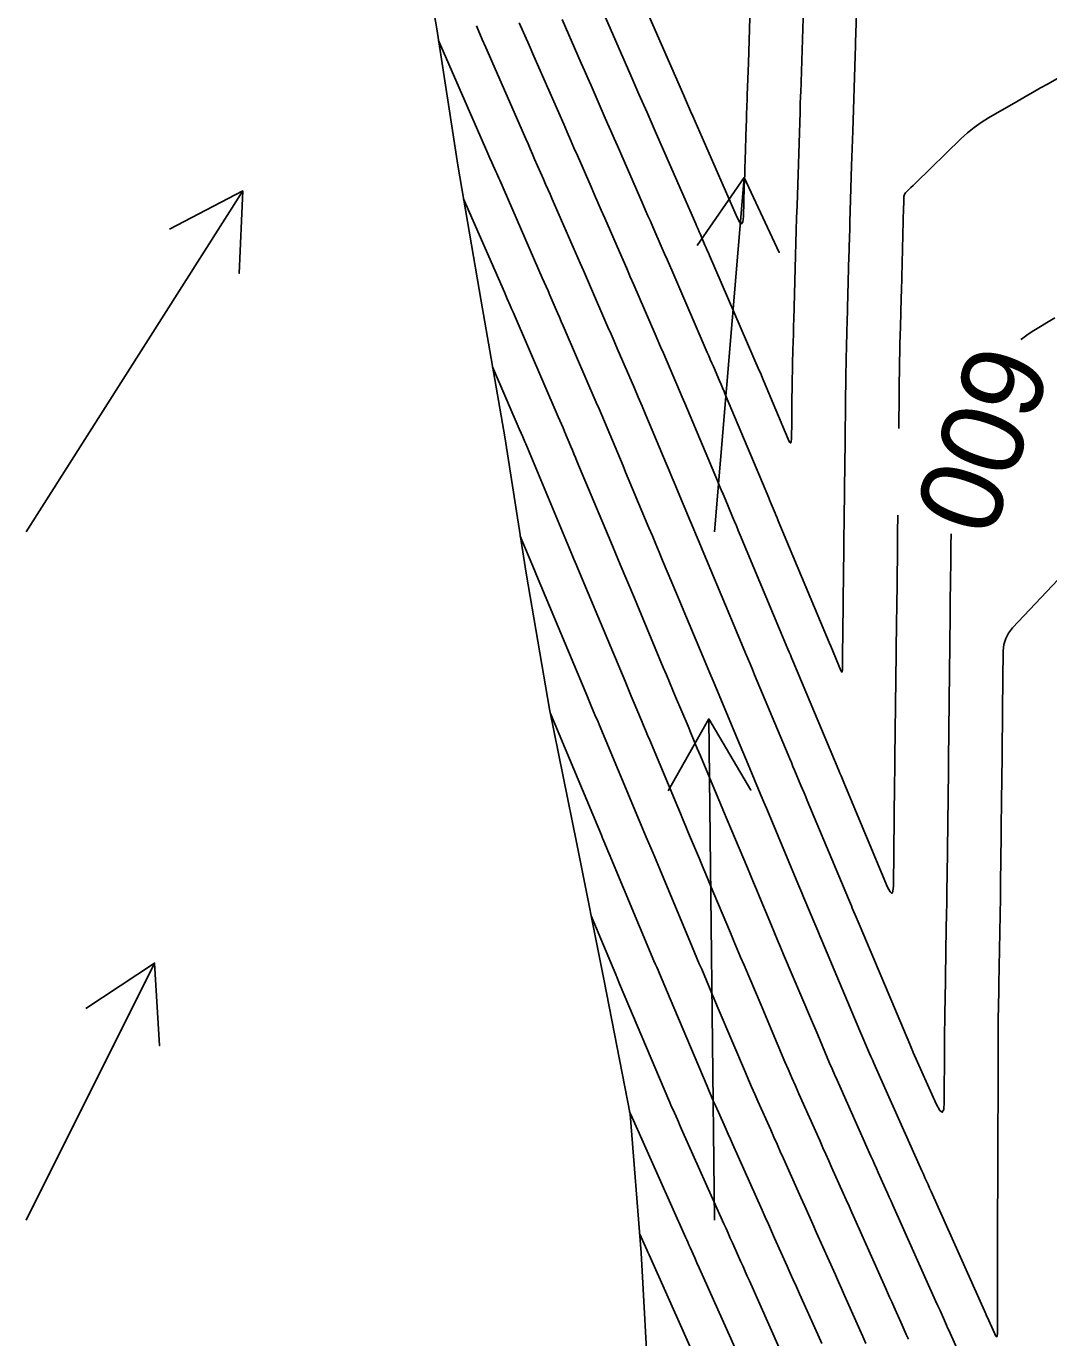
# Model space of a CAD drawing. Extents: x 954385 to 988206, y 1868364 to 1924553.
# Drawn here: x 957957.1 to 958031.4, y 1918710.4 to 1918805.7 of the extents above; entities that cross this region are included whole.
import ezdxf

# ---------------------------------------------------------------- set-up
doc = ezdxf.new("R2010")
doc.units = 0
for name, color, linetype in [('Ex_Contour Labels', 7, 'Continuous'), ('Ex_Major Contours', 7, 'Continuous'), ('Ex_Minor Contours', 7, 'Continuous'), ('Perimeter', 7, 'Continuous'), ('Slopes', 7, 'Continuous')]:
    doc.layers.add(name, color=color, linetype=linetype)

msp = doc.modelspace()

# ---------------------------------------------------------------- linework, layer by layer
at = {"layer": 'Ex_Major Contours'}
for points in [[(957989.838, 1918805.686), (957990.266, 1918804.707), (957990.523, 1918804.12), (957993.431, 1918797.475), (957993.591, 1918797.11), (957993.75, 1918796.745), (957993.91, 1918796.38), (957994.07, 1918796.015), (957994.708, 1918794.555), (957994.868, 1918794.19), (957995.028, 1918793.825), (957995.188, 1918793.46), (957995.347, 1918793.095), (957997.384, 1918788.442), (957997.609, 1918787.927), (957997.834, 1918787.413), (957998.057, 1918786.898), (957998.281, 1918786.382), (957999.173, 1918784.321), (957999.396, 1918783.806), (957999.619, 1918783.291), (957999.842, 1918782.775), (958000.064, 1918782.26), (958001.316, 1918779.367), (958001.595, 1918778.719), (958001.872, 1918778.07), (958002.148, 1918777.42), (958002.422, 1918776.769), (958003.623, 1918773.902), (958003.841, 1918773.382), (958004.059, 1918772.862), (958004.277, 1918772.342), (958004.495, 1918771.822), (958005.366, 1918769.743), (958005.584, 1918769.223), (958005.801, 1918768.703), (958006.019, 1918768.183), (958006.237, 1918767.663), (958008.244, 1918762.868), (958008.737, 1918761.69), (958009.395, 1918760.12), (958009.559, 1918759.728), (958009.724, 1918759.335), (958009.888, 1918758.943), (958010.052, 1918758.55), (958012.49, 1918752.728), (958012.606, 1918752.452), (958012.722, 1918752.176), (958012.837, 1918751.9), (958012.953, 1918751.624), (958013.416, 1918750.519), (958013.532, 1918750.243), (958013.647, 1918749.967), (958013.763, 1918749.691), (958013.879, 1918749.415), (958016.87, 1918742.276), (958016.94, 1918742.108), (958017.011, 1918741.94), (958017.081, 1918741.773), (958017.151, 1918741.605), (958017.432, 1918740.934), (958017.503, 1918740.766), (958017.573, 1918740.599), (958017.644, 1918740.431), (958017.714, 1918740.264), (958021.331, 1918731.715), (958021.482, 1918731.358), (958021.508, 1918731.298), (958021.533, 1918731.239), (958021.559, 1918731.18), (958021.585, 1918731.121), (958023.254, 1918727.387), (958023.505, 1918726.913), (958023.685, 1918726.775), (958023.793, 1918726.974), (958023.831, 1918727.509), (958023.841, 1918731.38), (958023.841, 1918731.569), (958023.843, 1918731.757), (958023.845, 1918731.946), (958023.848, 1918732.134), (958023.862, 1918732.954), (958023.864, 1918733.109), (958023.867, 1918733.265), (958023.869, 1918733.421), (958023.872, 1918733.577), (958023.885, 1918734.356), (958023.89, 1918734.667), (958023.893, 1918734.823), (958023.982, 1918740.161), (958023.997, 1918741.103), (958024.011, 1918742.044), (958024.024, 1918742.986), (958024.036, 1918743.927), (958024.129, 1918751.585), (958024.136, 1918752.166), (958024.138, 1918752.343), (958024.138, 1918752.365), (958024.214, 1918758.741), (958024.218, 1918759.127), (958024.223, 1918759.512), (958024.227, 1918759.898), (958024.232, 1918760.283), (958024.268, 1918763.368), (958024.297, 1918765.809), (958024.303, 1918766.345), (958024.309, 1918766.88), (958024.315, 1918767.416), (958024.322, 1918767.951), (958024.332, 1918768.784)], [(958029.404, 1918782.901), (958029.447, 1918782.938), (958029.828, 1918783.225), (958030.23, 1918783.488), (958031.876, 1918784.488)], [(957995.217, 1918755.74), (957998.918, 1918746.911), (957999.013, 1918746.683), (957999.109, 1918746.455), (957999.3, 1918745.999), (957999.395, 1918745.771), (957999.491, 1918745.543), (958002.743, 1918737.778), (958002.84, 1918737.546), (958002.938, 1918737.315), (958003.035, 1918737.083), (958003.133, 1918736.852), (958003.916, 1918735.002), (958006.6, 1918728.657), (958006.75, 1918728.306), (958006.901, 1918727.956), (958007.053, 1918727.607), (958007.208, 1918727.259), (958007.83, 1918725.867), (958007.985, 1918725.519), (958008.141, 1918725.171), (958008.296, 1918724.823), (958008.452, 1918724.475), (958010.605, 1918719.651), (958010.831, 1918719.145), (958011.057, 1918718.639), (958011.283, 1918718.133), (958011.509, 1918717.627), (958012.414, 1918715.603), (958012.64, 1918715.097), (958012.866, 1918714.591), (958013.092, 1918714.085), (958013.318, 1918713.579), (958014.64, 1918710.621), (958014.93, 1918709.973)]]:
    msp.add_lwpolyline(points, dxfattribs=at)
at = {"layer": 'Ex_Minor Contours'}
for points in [[(958009.811, 1918809.565), (958009.598, 1918803.001), (958009.521, 1918800.652), (958009.509, 1918800.281), (958009.497, 1918799.91), (958009.473, 1918799.169), (958009.461, 1918798.798), (958009.449, 1918798.427), (958009.367, 1918795.907), (958009.351, 1918795.426), (958009.336, 1918794.944), (958009.32, 1918794.462), (958009.304, 1918793.981), (958009.235, 1918791.851), (958009.194, 1918791.458), (958009.106, 1918791.313), (958008.971, 1918791.415), (958008.788, 1918791.765), (958005.569, 1918799.122), (958005.404, 1918799.498), (958004.966, 1918800.501), (958004.911, 1918800.626), (958001.612, 1918808.165)], [(958017.511, 1918808.051), (958017.395, 1918804.48), (958017.387, 1918804.235), (958017.379, 1918803.991), (958017.371, 1918803.746), (958017.363, 1918803.501), (958017.185, 1918798.045), (958017.165, 1918797.411), (958017.144, 1918796.778), (958017.124, 1918796.144), (958017.103, 1918795.511), (958016.997, 1918792.249), (958016.989, 1918791.979), (958016.98, 1918791.71), (958016.972, 1918791.44), (958016.965, 1918791.171), (958016.936, 1918790.092), (958016.928, 1918789.823), (958016.921, 1918789.553), (958016.914, 1918789.284), (958016.906, 1918789.014), (958016.802, 1918785.205), (958016.792, 1918784.824), (958016.781, 1918784.444), (958016.771, 1918784.063), (958016.761, 1918783.682), (958016.719, 1918782.159), (958016.709, 1918781.778), (958016.701, 1918781.397), (958016.694, 1918781.016), (958016.689, 1918780.636), (958016.655, 1918777.856), (958016.648, 1918777.266), (958016.641, 1918776.676), (958016.634, 1918776.085), (958016.627, 1918775.495), (958016.585, 1918772.075), (958016.579, 1918771.598), (958016.574, 1918771.121), (958016.568, 1918770.643), (958016.562, 1918770.166), (958016.538, 1918768.041), (958016.533, 1918767.672), (958016.529, 1918767.302), (958016.525, 1918766.933), (958016.52, 1918766.563), (958016.503, 1918765.085), (958016.499, 1918764.715), (958016.494, 1918764.346), (958016.49, 1918763.976), (958016.486, 1918763.606), (958016.441, 1918759.895), (958016.438, 1918759.641), (958016.435, 1918759.386), (958016.429, 1918758.878), (958016.422, 1918758.781), (958016.403, 1918758.746), (958016.371, 1918758.771), (958016.328, 1918758.858), (958015.588, 1918760.625), (958015.479, 1918760.885), (958011.772, 1918769.742), (958011.714, 1918769.879), (958011.656, 1918770.017), (958011.599, 1918770.155), (958011.541, 1918770.292), (958011.253, 1918770.98), (958011.137, 1918771.255), (958011.08, 1918771.393), (958007.948, 1918778.866), (958007.839, 1918779.125), (958007.729, 1918779.385), (958007.618, 1918779.644), (958007.507, 1918779.902), (958007.06, 1918780.937), (958006.948, 1918781.195), (958006.836, 1918781.454), (958006.724, 1918781.712), (958006.612, 1918781.971), (958004.031, 1918787.935), (958003.859, 1918788.331), (958003.688, 1918788.726), (958003.515, 1918789.122), (958003.342, 1918789.517), (958002.65, 1918791.098), (958002.477, 1918791.494), (958002.304, 1918791.889), (958002.131, 1918792.284), (958001.958, 1918792.68), (958000.084, 1918796.963), (957999.844, 1918797.511), (957999.605, 1918798.059), (957999.365, 1918798.607), (957999.125, 1918799.155), (957998.166, 1918801.347), (957997.926, 1918801.895), (957997.686, 1918802.443), (957997.446, 1918802.991), (957997.206, 1918803.539), (957996.062, 1918806.154)], [(957998.875, 1918807.072), (958001.059, 1918802.083), (958001.353, 1918801.409), (958001.648, 1918800.736), (958002.237, 1918799.389), (958002.385, 1918799.052), (958002.532, 1918798.716), (958002.679, 1918798.379), (958002.827, 1918798.042), (958005.774, 1918791.305), (958005.858, 1918791.113), (958005.942, 1918790.921), (958006.026, 1918790.729), (958006.111, 1918790.537), (958006.447, 1918789.768), (958006.531, 1918789.576), (958006.615, 1918789.383), (958006.698, 1918789.191), (958006.782, 1918788.999), (958010.391, 1918780.659), (958010.471, 1918780.474), (958010.604, 1918780.166), (958010.631, 1918780.104), (958010.657, 1918780.042), (958010.684, 1918779.98), (958010.71, 1918779.918), (958012.49, 1918775.67), (958012.596, 1918775.458), (958012.672, 1918775.396), (958012.719, 1918775.482), (958012.737, 1918775.718), (958012.752, 1918776.959), (958012.756, 1918777.269), (958012.76, 1918777.579), (958012.764, 1918777.889), (958012.767, 1918778.199), (958012.787, 1918779.786), (958012.792, 1918780.154), (958012.799, 1918780.522), (958012.807, 1918780.89), (958012.816, 1918781.258), (958012.858, 1918782.807), (958012.869, 1918783.188), (958012.879, 1918783.568), (958012.889, 1918783.949), (958012.9, 1918784.33), (958013.027, 1918789.017), (958013.053, 1918789.926), (958013.079, 1918790.834), (958013.107, 1918791.742), (958013.136, 1918792.65), (958013.355, 1918799.414), (958013.372, 1918799.933), (958013.396, 1918800.654), (958013.401, 1918800.822), (958013.604, 1918807.033)], [(957992.95, 1918805.92), (957993.663, 1918804.292), (957994.019, 1918803.477), (957994.375, 1918802.663), (957996.18, 1918798.538), (957996.429, 1918797.97), (957996.677, 1918797.402), (957996.926, 1918796.834), (957997.175, 1918796.266), (957998.169, 1918793.993), (957998.417, 1918793.425), (957998.666, 1918792.857), (957998.915, 1918792.289), (957999.163, 1918791.721), (958000.238, 1918789.267), (958000.499, 1918788.668), (958000.76, 1918788.069), (958001.021, 1918787.47), (958001.28, 1918786.871), (958002.833, 1918783.283), (958003.03, 1918782.828), (958003.227, 1918782.372), (958003.424, 1918781.917), (958003.621, 1918781.461), (958004.409, 1918779.639), (958004.606, 1918779.184), (958004.801, 1918778.727), (958004.994, 1918778.27), (958005.187, 1918777.813), (958007.352, 1918772.647), (958007.489, 1918772.319), (958007.627, 1918771.99), (958007.765, 1918771.661), (958007.903, 1918771.332), (958008.453, 1918770.018), (958008.591, 1918769.689), (958008.729, 1918769.36), (958008.867, 1918769.031), (958009.004, 1918768.703), (958011.867, 1918761.865), (958012.477, 1918760.408), (958012.564, 1918760.2), (958012.651, 1918759.992), (958012.738, 1918759.784), (958012.825, 1918759.576), (958016.17, 1918751.587), (958016.251, 1918751.395), (958016.332, 1918751.202), (958016.534, 1918750.72), (958016.655, 1918750.431), (958019.712, 1918743.136), (958019.892, 1918742.774), (958020.023, 1918742.667), (958020.104, 1918742.815), (958020.135, 1918743.218), (958020.225, 1918750.666), (958020.229, 1918750.978), (958020.234, 1918751.368), (958020.235, 1918751.523), (958020.236, 1918751.601), (958020.248, 1918752.579), (958020.337, 1918760.107), (958020.347, 1918760.914), (958020.356, 1918761.721), (958020.366, 1918762.528), (958020.375, 1918763.335), (958020.424, 1918767.494), (958020.432, 1918768.178), (958020.44, 1918768.863), (958020.455, 1918770.152)], [(958020.531, 1918776.453), (958020.591, 1918781.443), (958020.597, 1918781.858), (958020.605, 1918782.273), (958020.614, 1918782.688), (958020.624, 1918783.104), (958020.669, 1918784.764), (958020.681, 1918785.179), (958020.692, 1918785.595), (958020.703, 1918786.01), (958020.715, 1918786.425), (958020.88, 1918792.521), (958020.881, 1918792.553), (958020.882, 1918792.586), (958020.883, 1918792.618), (958020.884, 1918792.651), (958020.893, 1918792.91), (958020.905, 1918793.297), (958020.914, 1918793.369), (958020.936, 1918793.436), (958020.971, 1918793.497), (958021.018, 1918793.553), (958021.412, 1918793.938), (958021.579, 1918794.102), (958021.747, 1918794.265), (958025.06, 1918797.506), (958025.518, 1918797.927), (958026.001, 1918798.317), (958026.507, 1918798.675), (958027.037, 1918799.002), (958029.205, 1918800.245), (958029.747, 1918800.556), (958030.289, 1918800.866), (958030.831, 1918801.177), (958031.373, 1918801.488), (958037.89, 1918805.224)], [(958032.523, 1918765.905), (958028.798, 1918761.954), (958028.507, 1918761.586), (958028.298, 1918761.185), (958028.171, 1918760.752), (958028.124, 1918760.286), (958028.075, 1918756.046), (958028.071, 1918755.761), (958028.068, 1918755.476), (958028.064, 1918755.191), (958028.061, 1918754.906), (958028.048, 1918753.766), (958028.044, 1918753.481), (958028.041, 1918753.197), (958028.037, 1918752.912), (958028.034, 1918752.627), (958027.994, 1918749.382), (958027.986, 1918748.746), (958027.979, 1918748.11), (958027.971, 1918747.474), (958027.963, 1918746.838), (958027.922, 1918743.461), (958027.919, 1918743.191), (958027.915, 1918742.92), (958027.911, 1918742.649), (958027.907, 1918742.379), (958027.802, 1918736.076), (958027.791, 1918735.388), (958027.779, 1918734.699), (958027.756, 1918733.322), (958027.751, 1918732.977), (958027.747, 1918732.633), (958027.744, 1918732.289), (958027.743, 1918731.944), (958027.717, 1918721.437), (958027.712, 1918719.555), (958027.711, 1918719.085), (958027.71, 1918718.614), (958027.709, 1918718.144), (958027.707, 1918717.673), (958027.694, 1918712.593), (958027.694, 1918712.359), (958027.693, 1918712.124), (958027.693, 1918711.89), (958027.692, 1918711.655), (958027.69, 1918710.714), (958027.678, 1918710.537), (958027.642, 1918710.471), (958027.582, 1918710.516), (958027.499, 1918710.674), (958026.944, 1918711.917), (958026.912, 1918711.988), (958026.848, 1918712.132), (958022.879, 1918721.016), (958022.767, 1918721.267), (958022.655, 1918721.517), (958022.431, 1918722.018), (958022.319, 1918722.269), (958022.207, 1918722.52), (958018.814, 1918730.116), (958018.71, 1918730.349), (958018.608, 1918730.583), (958018.507, 1918730.818), (958018.406, 1918731.053), (958017.71, 1918732.7), (958014.938, 1918739.252), (958014.792, 1918739.597), (958014.646, 1918739.942), (958014.501, 1918740.288), (958014.356, 1918740.633), (958013.777, 1918742.015), (958013.632, 1918742.361), (958013.488, 1918742.707), (958013.343, 1918743.052), (958013.198, 1918743.398), (958011.103, 1918748.399), (958010.912, 1918748.854), (958010.72, 1918749.31), (958010.529, 1918749.766), (958010.338, 1918750.222), (958009.574, 1918752.045), (958009.383, 1918752.501), (958009.192, 1918752.957), (958009.001, 1918753.413), (958008.81, 1918753.869), (958007.279, 1918757.524), (958007.038, 1918758.101), (958006.796, 1918758.678), (958006.555, 1918759.255), (958006.313, 1918759.832), (958005.105, 1918762.717), (958004.38, 1918764.448), (958003.372, 1918766.858), (958003.123, 1918767.452), (958002.874, 1918768.046), (958002.625, 1918768.64), (958002.376, 1918769.234), (958000.877, 1918772.814), (958000.684, 1918773.274), (958000.491, 1918773.734), (958000.298, 1918774.194), (958000.106, 1918774.654), (957999.334, 1918776.494), (957999.141, 1918776.954), (957998.946, 1918777.413), (957998.75, 1918777.872), (957998.553, 1918778.33), (957996.286, 1918783.572), (957996.148, 1918783.891), (957996.01, 1918784.209), (957995.872, 1918784.527), (957995.735, 1918784.846), (957995.183, 1918786.119), (957995.045, 1918786.438), (957994.907, 1918786.756), (957994.768, 1918787.074), (957994.629, 1918787.392), (957991.531, 1918794.47), (957991.46, 1918794.632), (957991.39, 1918794.793), (957991.319, 1918794.955), (957991.248, 1918795.117), (957990.965, 1918795.765), (957990.823, 1918796.088), (957990.681, 1918796.412), (957987.086, 1918804.628)], [(957988.907, 1918793.121), (957991.875, 1918786.342), (957991.928, 1918786.221), (957991.981, 1918786.099), (957992.033, 1918785.978), (957992.086, 1918785.856), (957992.296, 1918785.37), (957992.401, 1918785.127), (957992.507, 1918784.884), (957995.79, 1918777.293), (957995.905, 1918777.025), (957996.02, 1918776.757), (957996.134, 1918776.488), (957996.247, 1918776.22), (957996.698, 1918775.144), (957996.81, 1918774.875), (957996.923, 1918774.606), (957997.036, 1918774.337), (957997.148, 1918774.068), (957999.604, 1918768.208), (957999.775, 1918767.799), (957999.947, 1918767.389), (958000.118, 1918766.98), (958000.29, 1918766.57), (958001.318, 1918764.113), (958001.661, 1918763.294), (958003.42, 1918759.092), (958003.645, 1918758.557), (958003.869, 1918758.021), (958004.093, 1918757.486), (958004.317, 1918756.951), (958005.214, 1918754.809), (958005.438, 1918754.274), (958005.662, 1918753.739), (958005.887, 1918753.203), (958006.111, 1918752.668), (958007.261, 1918749.925), (958007.527, 1918749.289), (958007.794, 1918748.653), (958008.06, 1918748.018), (958008.326, 1918747.382), (958009.526, 1918744.519), (958009.745, 1918743.996), (958009.965, 1918743.473), (958010.184, 1918742.949), (958010.403, 1918742.426), (958011.28, 1918740.332), (958011.499, 1918739.809), (958011.719, 1918739.285), (958011.94, 1918738.763), (958012.161, 1918738.24), (958014.113, 1918733.626), (958014.635, 1918732.392), (958015.331, 1918730.748), (958015.506, 1918730.337), (958015.683, 1918729.927), (958015.862, 1918729.518), (958016.043, 1918729.11), (958018.508, 1918723.591), (958018.641, 1918723.292), (958018.775, 1918722.994), (958018.908, 1918722.696), (958019.041, 1918722.398), (958019.573, 1918721.206), (958019.706, 1918720.908), (958019.839, 1918720.61), (958019.973, 1918720.312), (958020.106, 1918720.014), (958023.205, 1918713.076), (958023.365, 1918712.72), (958023.524, 1918712.364), (958023.842, 1918711.652), (958023.921, 1918711.474), (958024.001, 1918711.296), (958024.08, 1918711.117), (958024.16, 1918710.939), (958027.83, 1918702.717)], [(957991.013, 1918780.913), (957993.027, 1918776.255), (957993.061, 1918776.178), (957993.094, 1918776.1), (957993.127, 1918776.023), (957993.16, 1918775.945), (957993.355, 1918775.478), (957993.42, 1918775.322), (957996.831, 1918767.182), (957996.925, 1918766.957), (957997.019, 1918766.732), (957997.114, 1918766.507), (957997.208, 1918766.282), (957997.962, 1918764.482), (958000.644, 1918758.076), (958000.793, 1918757.72), (958000.941, 1918757.364), (958001.09, 1918757.009), (958001.239, 1918756.653), (958001.835, 1918755.231), (958001.984, 1918754.875), (958002.133, 1918754.52), (958002.282, 1918754.164), (958002.431, 1918753.809), (958004.473, 1918748.936), (958004.67, 1918748.466), (958004.867, 1918747.997), (958005.064, 1918747.527), (958005.26, 1918747.057), (958006.048, 1918745.178), (958006.245, 1918744.708), (958006.441, 1918744.239), (958006.638, 1918743.769), (958006.835, 1918743.299), (958008.302, 1918739.796), (958008.547, 1918739.212), (958008.792, 1918738.629), (958009.038, 1918738.045), (958009.285, 1918737.462), (958010.518, 1918734.548), (958011.258, 1918732.799), (958012.255, 1918730.443), (958012.504, 1918729.856), (958012.757, 1918729.271), (958013.013, 1918728.687), (958013.271, 1918728.105), (958014.809, 1918724.662), (958015.02, 1918724.191), (958015.23, 1918723.72), (958015.44, 1918723.249), (958015.65, 1918722.778), (958016.491, 1918720.895), (958016.702, 1918720.424), (958016.912, 1918719.953), (958017.122, 1918719.482), (958017.333, 1918719.011), (958019.563, 1918714.02), (958019.714, 1918713.682), (958019.865, 1918713.344), (958020.016, 1918713.005), (958020.167, 1918712.667), (958020.772, 1918711.315), (958020.923, 1918710.977), (958021.074, 1918710.639), (958021.225, 1918710.3)], [(958018.146, 1918709.982), (958017.924, 1918710.48), (958017.701, 1918710.978), (958016.811, 1918712.971), (958016.588, 1918713.469), (958016.366, 1918713.967), (958016.143, 1918714.466), (958015.92, 1918714.964), (958014.56, 1918718.009), (958014.272, 1918718.653), (958013.985, 1918719.296), (958013.697, 1918719.94), (958013.41, 1918720.583), (958012.151, 1918723.404), (958011.918, 1918723.925), (958011.685, 1918724.445), (958011.453, 1918724.966), (958011.22, 1918725.487), (958010.29, 1918727.57), (958010.058, 1918728.091), (958009.829, 1918728.614), (958009.603, 1918729.138), (958009.38, 1918729.662), (958007.414, 1918734.308), (958006.898, 1918735.529), (958006.209, 1918737.157), (958006.037, 1918737.564), (958005.865, 1918737.972), (958005.694, 1918738.379), (958005.523, 1918738.787), (958003.163, 1918744.421), (958003.041, 1918744.713), (958002.918, 1918745.005), (958002.796, 1918745.297), (958002.674, 1918745.589), (958002.185, 1918746.756), (958002.062, 1918747.048), (958001.94, 1918747.34), (958001.818, 1918747.632), (958001.695, 1918747.924), (957998.75, 1918754.949), (957998.677, 1918755.125), (957998.603, 1918755.301), (957998.529, 1918755.477), (957998.456, 1918755.653), (957998.161, 1918756.356), (957998.014, 1918756.707), (957997.867, 1918757.059), (957994.211, 1918765.791), (957994.109, 1918766.035), (957994.058, 1918766.157), (957993.03, 1918768.611)], [(957998.176, 1918741.036), (957999.964, 1918736.769), (957999.987, 1918736.713), (958000.01, 1918736.658), (958000.034, 1918736.603), (958000.057, 1918736.547), (958000.244, 1918736.104), (958003.821, 1918727.651), (958003.896, 1918727.475), (958003.972, 1918727.299), (958004.049, 1918727.123), (958004.127, 1918726.948), (958004.44, 1918726.247), (958004.518, 1918726.072), (958004.596, 1918725.896), (958004.674, 1918725.721), (958004.753, 1918725.546), (958007.821, 1918718.674), (958007.976, 1918718.328), (958008.13, 1918717.982), (958008.285, 1918717.637), (958008.439, 1918717.291), (958009.057, 1918715.907), (958009.212, 1918715.561), (958009.366, 1918715.215), (958009.521, 1918714.869), (958009.676, 1918714.523), (958011.845, 1918709.669)], [(958000.964, 1918726.829), (958001.041, 1918726.646), (958001.045, 1918726.636), (958001.054, 1918726.617), (958005.037, 1918717.697), (958005.12, 1918717.511), (958005.203, 1918717.326), (958005.286, 1918717.14), (958005.369, 1918716.954), (958005.701, 1918716.21), (958005.867, 1918715.839), (958006.033, 1918715.467), (958009.049, 1918708.717)], [(958001.691, 1918717.976), (958002.252, 1918716.72), (958002.298, 1918716.617), (958002.39, 1918716.411), (958006.254, 1918707.765)]]:
    msp.add_lwpolyline(points, dxfattribs=at)
at = {"layer": 'Perimeter'}
msp.add_lwpolyline([(958002.36, 1918706.439), (958001.804, 1918716.563), (958001.002, 1918726.632), (957999.088, 1918736.451), (957997.137, 1918746.262), (957995.151, 1918756.065), (957993.448, 1918765.931), (957991.903, 1918775.833), (957990.175, 1918785.694), (957988.49, 1918795.565), (957986.956, 1918805.469), (957985.254, 1918815.336), (957982.15, 1918824.888), (957981.062, 1918828.744), (957980.363, 1918834.736), (957977.937, 1918844.44), (957974.671, 1918853.956), (957971.691, 1918863.536)], dxfattribs=at)
at = {"layer": 'Slopes'}
for points in [[(958007.131, 1918768.928), (958009.293, 1918794.663), (958011.848, 1918789.234), (958009.293, 1918794.663), (958005.869, 1918789.736)], [(957957.131, 1918768.928), (957972.862, 1918793.705), (957972.609, 1918787.71), (957972.862, 1918793.705), (957967.544, 1918790.926)], [(958007.131, 1918718.928), (958006.723, 1918755.342), (958009.781, 1918750.18), (958006.723, 1918755.342), (958003.781, 1918750.112)], [(957957.131, 1918718.928), (957966.462, 1918737.61), (957966.824, 1918731.621), (957966.462, 1918737.61), (957961.457, 1918734.302)]]:
    msp.add_lwpolyline(points, dxfattribs=at)

# ---------------------------------------------------------------- texts
at = {"layer": 'Ex_Contour Labels'}
msp.add_text('600', height=6, rotation=250.57316, dxfattribs=at).set_placement((958026.008, 1918782.963))

doc.saveas('drawing.dxf')
